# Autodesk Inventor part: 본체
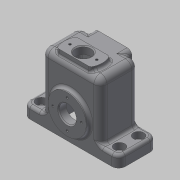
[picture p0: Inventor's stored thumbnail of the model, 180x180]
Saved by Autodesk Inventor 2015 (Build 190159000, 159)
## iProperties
Created: 2023-12
Part Number: 본체
Material: 일반
Document SubType Name: Modeling
Designer: 10415
Density: 1 g/cm^3
Appearance: 기본값
Mass: 81.4468 g
Surface Area: 358.777 cm^2
Volume: 81.4468 cm^3
Author: 10415
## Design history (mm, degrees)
sketch "스케치1"
  geometry: L1 (31, 20)-(-31, 20); L2 (-31, 20)-(-31, -20); L3 (-31, -20)-(31, -20); L4 (31, -20)-(31, 20); L5 (31, 20)-(-31, -20); L6 (-31, 20)-(31, -20); 1 further point
  constraints: 12 end point, 2 midpoint, 2 parallel, 1 horizontal, 1 perpendicular
  dimensions: "d0" = 62 distance of L2.end L3.end; "d1" = 40 distance of L1.end L2.end
extrude "돌출1" new body sketch "스케치1" distance "d2" = 72; taper "d3" = 0 deg
fillet "모깎기1" dims "d8" = 7
fillet "모깎기2" dims "d9" = 7
feature "쉘1" dims "d10" = 4
sketch "스케치3"
  geometry: L1 (50, -20)-(-50, -20); L2 (-50, -20)-(-50, 20); L3 (-50, 20)-(50, 20); L4 (50, 20)-(50, -20); L5 (50, -20)-(-50, 20); L6 (-50, -20)-(50, 20); L7 (27, -13)-(27, 13) reference; L8 (24, 16)-(-24, 16) reference; L9 (-27, 13)-(-27, -13) reference; L10 (-24, -16)-(24, -16) reference; L11 (-24, -20)-(24, -20) reference; L12 (-31, 13)-(-31, -13) reference; L13 (24, 20)-(-24, 20) reference; L14 (31, -13)-(31, 13) reference; A1 r 3 centre (24, -13) between (24, -16) and (27, -13) reference; A2 r 3 centre (24, 13) between (27, 13) and (24, 16) reference; A3 r 3 centre (-24, 13) between (-24, 16) and (-27, 13) reference; A4 r 3 centre (-24, -13) between (-27, -13) and (-24, -16) reference; A5 r 7 centre (24, -13) between (24, -20) and (31, -13) reference; A6 r 7 centre (-24, -13) between (-31, -13) and (-24, -20) reference; A7 r 7 centre (-24, 13) between (-24, 20) and (-31, 13) reference; A8 r 7 centre (24, 13) between (31, 13) and (24, 20) reference; 1 further point
  constraints: 12 end point, 2 midpoint, 2 parallel, 1 horizontal, 1 perpendicular
  dimensions: "d11" = 100 distance of L2.end L3.end; "d12" = 40 distance of L1.end L2.end
extrude "돌출3" join sketch "스케치3" distance "d13" = 12; taper "d14" = 0 deg
fillet "모깎기3" dims "d15" = 7
sketch "스케치4"
  geometry: L1 (-24, 20)-(-43, 20) reference; 3 further points
  constraints: 1 vertical alignment
  dimensions: "d16" = 10 distance from line of L1 point (-41, 10); "d17" = 20 distance of point (-41, 10) point (-41, -10); "d18" = 41 horizontal distance of point (0, 0) point (-41, 10)
hole "구멍1" sketch "스케치4" at (-41, 10), (-41, -10) diameter "d19" = 6.6; stored, may be unused: countersink angle "d23" = 90 deg, drill point angle "d25" = 118 deg; dims "d20" = 6, "d21" = 11, "d22" = 6.6, "d24" = 8
sketch "스케치5"
  geometry: L1 (67, -65)-(-19, -65) reference; C1 r 20 at (24, -37); 2 further points
  constraints: 1 centre point, 1 midpoint, 1 vertical alignment
  dimensions: "d26" = 28 distance of point (24, -65) C1.centre; "d36" = 40 diameter of C1
extrude "돌출4" join sketch "스케치5" distance "d27" = 4; taper "d28" = 0 deg
sketch "스케치6"
  geometry: C1 r 20 at (0, 0) reference; C2 r 9 at (0, 0); 1 further point
  constraints: 1 centre point, 1 coincident
  dimensions: "d29" = 18 diameter of C2
extrude "돌출5" cut sketch "스케치6" distance "d30" = 10; taper "d31" = 0 deg
chamfer "모따기1" distance "d32" = 1; stored, may be unused: second distance "d33" = 2, angle "d34" = 45 deg
sketch "스케치7"
  geometry: C1 r 20 at (0, 0) reference; 2 further points
  constraints: 1 vertical alignment
  dimensions: "d35" = 15 distance of C1.centre point (0, 15)
hole "구멍2" sketch "스케치7" at (0, 15) diameter "d37" = 2.459; stored, may be unused: countersink angle "d41" = 90 deg, drill point angle "d43" = 118 deg; dims "d38" = 6, "d39" = 11, "d40" = 6.6, "d42" = 10
sketch "스케치8"
  geometry: L1 (-19, -65)-(67, -65) reference; C1 r 12 at (24, -37); 2 further points
  constraints: 1 centre point, 1 midpoint, 1 vertical alignment
  dimensions: "d47" = 28 distance of point (24, -65) C1.centre; "d48" = 24 diameter of C1
extrude "돌출6" join sketch "스케치8" distance "d49" = 4; taper "d50" = 0 deg
sketch "스케치9"
  geometry: C1 r 12 at (0, 0) reference; 1 further point
hole "구멍3" sketch "스케치9" at (0, 0) diameter "d51" = 13.835; stored, may be unused: countersink angle "d55" = 90 deg, drill point angle "d57" = 118 deg; dims "d52" = 32, "d53" = 11, "d54" = 6.6, "d56" = 10
sketch "스케치10"
  geometry: L1 (-19, -65)-(67, -65) reference; L2 (4, -17)-(44, -17); L3 (44, -17)-(44, 7); L4 (44, 7)-(4, 7); L5 (4, 7)-(4, -17); L6 (4, -17)-(44, 7); L7 (44, -17)-(4, 7); L8 (48, 7)-(0, 7) reference; 5 further points
  constraints: 12 end point, 6 midpoint, 2 parallel, 1 horizontal, 1 perpendicular, 1 vertical alignment
  dimensions: "d58" = 40 distance of L3.end L4.end; "d59" = 24 distance of L2.end L3.end
extrude "돌출7" join sketch "스케치10" distance "d60" = 4; taper "d62" = 0 deg; dims "d61" = 4, "d63" = 0
sketch "스케치11"
  geometry: L1 (44, 7)-(4, 7) reference; 3 further points
  constraints: 1 horizontal alignment
  dimensions: "d64" = 28 distance of point (10, 1) point (38, 1); "d65" = 6 distance from line of L1 point (10, 1); "d66" = 14 horizontal distance of point (24, -65) point (10, 1)
hole "구멍4" sketch "스케치11" at (10, 1), (38, 1) diameter "d67" = 2.459; stored, may be unused: countersink angle "d71" = 90 deg, drill point angle "d73" = 118 deg; dims "d68" = 6, "d69" = 11, "d70" = 6.6, "d72" = 10
sketch "스케치12"
  geometry: L1 (40, -8)-(0, -8) reference; L2 (0, -4)-(40, -4); L3 (40, -4)-(40, -12); L4 (40, -12)-(0, -12); L5 (0, -12)-(0, -4); L6 (0, -4)-(40, -12); L7 (40, -4)-(0, -12); 2 further points
  constraints: 12 end point, 3 midpoint, 2 parallel, 1 horizontal, 1 perpendicular
  dimensions: "d74" = 8 distance of L2.end L3.end
extrude "돌출8" join sketch "스케치12" distance "d75" = 4; taper "d76" = 0 deg
fillet "모깎기4" dims "d77" = 5
sketch "스케치13"
  geometry: L1 (-15, 24)-(15, 24) reference; L2 (21, 3)-(-21, 3); L3 (-21, 3)-(-21, -17); L4 (-21, -17)-(21, -17); L5 (21, -17)-(21, 3); L6 (21, 3)-(-21, -17); L7 (-21, 3)-(21, -17); A1 r 20 centre (0, -7) between (17.321, -17) and (17.321, 3); A2 r 20 centre (0, -7) between (-17.321, 3) and (-17.321, -17); 4 further points
  constraints: 12 end point, 4 midpoint, 4 point on circle, 4 point on line, 2 centre point, 2 parallel, 2 vertical alignment, 1 coincident, 1 horizontal, 1 perpendicular
  dimensions: "d79" = 31 distance from line of L1 A1.centre; "d80" = 20 distance of L2.end L3.end; "d81" = 42 distance of L3.end L4.end; "d82" = 20 radius of A2; "d83" = 20 radius of A1
extrude "돌출9" join sketch "스케치13" distance "d84" = 4; taper "d85" = 0 deg; dims "d101" = 4, "d102" = 0
sketch "스케치14"
  geometry: C1 r 8 at (0, -7); A1 r 20 centre (0, -7) between (-17.321, 3) and (-17.321, -17) reference; 1 further point
  constraints: 1 centre point, 1 coincident
  dimensions: "d86" = 16 diameter of C1
extrude "돌출10" cut sketch "스케치14" distance "d87" = 10; taper "d88" = 0 deg
sketch "스케치15"
  geometry: C1 r 8 at (0, -7) reference; 3 further points
  constraints: 2 horizontal alignment
  dimensions: "d89" = 28 distance of point (14, -7) point (-14, -7); "d90" = 14 distance of C1.centre point (-14, -7)
hole "구멍5" sketch "스케치15" at (-14, -7), (14, -7) diameter "d91" = 2.459; stored, may be unused: countersink angle "d95" = 90 deg, drill point angle "d97" = 118 deg; dims "d92" = 6, "d93" = 11, "d94" = 6.6, "d96" = 10
chamfer "모따기2" distance "d98" = 1; stored, may be unused: second distance "d99" = 2, angle "d100" = 45 deg
fillet "모깎기5" dims "d103" = 3
fillet "모깎기6" dims "d104" = 3
fillet "모깎기7" dims "d105" = 3
fillet "모깎기8" dims "d106" = 3
fillet "모깎기9" dims "d107" = 3
fillet "모깎기10" dims "d108" = 3
sketch "스케치16"
  geometry: L1 (26, -65)-(0, -65) reference; L2 (-11, -25)-(-11, -49) reference; 2 further points
  constraints: 1 other
  dimensions: "d109" = 40 distance from line of L1 point (12, -25); "d110" = 23 distance from line of L2 point (12, -25)
feature "엠보싱1" sketch "스케치16" dims "d111" = 0.5, "d112" = 0
node "솔리드1"
mirror "대칭1"
pattern_circular "원형 패턴1" dims angle "d45" = 360 deg
node "투영된 루프1"
